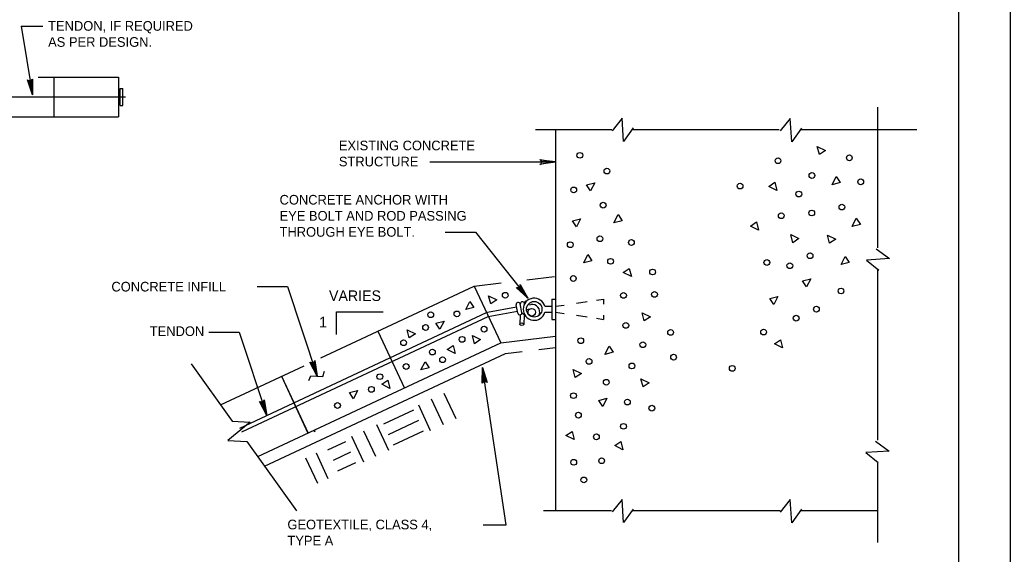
# Model space of a CAD drawing. Extents: x 638850 to 644908, y 297188 to 298900.
# Drawn here: x 640224.3 to 640532.4, y 298330.5 to 298496.6 of the extents above; entities that cross this region are included whole.
import ezdxf

# ---------------------------------------------------------------- set-up
doc = ezdxf.new("R2010")
doc.units = 0
for name, color, linetype in [('1', 7, 'Continuous'), ('3', 7, 'Continuous'), ('PLT-BNDY', 7, 'Continuous')]:
    doc.layers.add(name, color=color, linetype=linetype)

msp = doc.modelspace()

# ---------------------------------------------------------------- linework, layer by layer
at = {"layer": '1'}
for p, q in [((640516.44, 298068.53), (640516.44, 298632.53)), ((640224.78, 298494.68), (640228.26, 298473.3)), ((640255.62, 298470), (640255.62, 298475.29)), ((640256.38, 298470), (640256.38, 298475.29)), ((640077.89, 298472.64), (640257.22, 298472.64)), ((640366.11, 298430.58), (640382.39, 298410.09)), ((640382.12, 298415.82), (640390.71, 298416.87)), ((640307.6, 298413.71), (640316.88, 298385.84)), ((640318.01, 298391.53), (640365.68, 298413.83)), ((640365.68, 298413.83), (640374.04, 298414.84)), ((640365.68, 298413.83), (640373.94, 298396.17)), ((640389.85, 298409.8), (640390.98, 298409.8)), ((640403.75, 298409.46), (640405.9, 298409.78)), ((640369.85, 298405.69), (640378.84, 298407.34)), ((640370.08, 298404.41), (640379.13, 298406.07)), ((640379.25, 298405.39), (640378.77, 298408.04)), ((640380.53, 298405.61), (640380.04, 298408.3)), ((640381.35, 298408.35), (640381.32, 298408.51)), ((640381.98, 298406.59), (640383.52, 298406.87)), ((640382.36, 298407.99), (640383.28, 298408.16)), ((640387.69, 298407.56), (640389.85, 298407.56)), ((640390.98, 298407.56), (640393.69, 298407.96)), ((640397.52, 298408.53), (640400.83, 298409.03)), ((640292.84, 298369.71), (640369.53, 298405.59)), ((640293.39, 298368.53), (640370.08, 298404.41)), ((640322.91, 298398.79), (640322.91, 298405.81)), ((640379.99, 298404.83), (640379.85, 298402)), ((640381.29, 298404.76), (640381.15, 298401.93)), ((640387.69, 298405.72), (640389.85, 298405.72)), ((640389.85, 298403.48), (640390.98, 298403.48)), ((640390.98, 298405.72), (640393.69, 298405.32)), ((640397.52, 298404.75), (640400.83, 298404.25)), ((640403.75, 298403.82), (640405.9, 298403.5)), ((640292.58, 298399.47), (640301.19, 298373.62)), ((640335.71, 298399.81), (640343.97, 298382.15)), ((640373.94, 298396.17), (640390.98, 298398.24)), ((640298.36, 298360.81), (640373.94, 298396.17)), ((640385.84, 298394.15), (640390.98, 298394.77)), ((640300.5, 298357.82), (640375.47, 298392.89)), ((640375.47, 298392.89), (640380.65, 298393.52)), ((640277.67, 298389.7), (640290.43, 298371.88)), ((640286.81, 298376.93), (640312.77, 298389.08)), ((640375.63, 298339.62), (640368.27, 298388.53)), ((640305.74, 298385.79), (640314, 298368.13)), ((640305.79, 298385.81), (640314.06, 298368.15)), ((640352.34, 298378.75), (640356.05, 298370.83)), ((640356.26, 298380.58), (640359.97, 298372.66)), ((640346.8, 298375.3), (640337.45, 298370.92)), ((640348.34, 298376.88), (640352.04, 298368.96)), ((640335.29, 298370.77), (640339, 298362.85)), ((640348.34, 298372.02), (640338.98, 298367.64)), ((640315.87, 298368.58), (640316.33, 298368.79)), ((640315.92, 298368.6), (640316.37, 298368.81)), ((640327.52, 298367.14), (640331.23, 298359.22)), ((640331.25, 298368.88), (640334.95, 298360.96)), ((640349.87, 298368.73), (640340.52, 298364.36)), ((640295, 298365.5), (640310.44, 298343.94)), ((640325.71, 298365.43), (640320.09, 298362.8)), ((640313.25, 298360.46), (640316.95, 298352.54)), ((640316.5, 298361.98), (640320.2, 298354.06)), ((640327.24, 298362.15), (640321.79, 298359.6)), ((640328.78, 298358.87), (640323.22, 298356.27))]:
    msp.add_line(p, q, dxfattribs=at)
for points in [[(640228.09, 298477.95), (640227.79, 298477.72), (640228.26, 298473.3), (640228.09, 298477.95), (640228.26, 298478.21), (640228.26, 298473.3), (640227.33, 298477.64), (640226.98, 298477.75), (640228.26, 298473.3), (640226.72, 298477.96), (640226.98, 298477.75)], [(640415.19, 298463), (640412.18, 298458.77), (640411.72, 298466.01), (640408.62, 298462.1)], [(640467.51, 298462.98), (640464.5, 298458.74), (640464.04, 298465.99), (640460.93, 298462.08)], [(640386.37, 298453.02), (640386.54, 298452.68), (640390.98, 298452.43), (640386.37, 298453.02), (640386.13, 298453.22), (640390.98, 298452.43), (640386.54, 298452.22), (640386.38, 298451.89), (640390.98, 298452.43), (640386.13, 298451.67), (640386.38, 298451.89)], [(640490.7, 298425.39), (640494.93, 298422.38), (640487.69, 298421.92), (640491.6, 298418.81)], [(640379.97, 298414.06), (640379.82, 298413.72), (640382.39, 298410.09), (640379.97, 298414.06), (640379.98, 298414.37), (640382.39, 298410.09), (640379.45, 298413.43), (640379.09, 298413.35), (640382.39, 298410.09), (640378.77, 298413.41), (640379.09, 298413.35)], [(640315.98, 298390.4), (640315.71, 298390.13), (640316.88, 298385.84), (640315.98, 298390.4), (640316.09, 298390.69), (640316.88, 298385.84), (640315.27, 298389.98), (640314.91, 298390.03), (640316.88, 298385.84), (640314.62, 298390.2), (640314.91, 298390.03)], [(640368.38, 298383.88), (640368.69, 298384.1), (640368.27, 298388.53), (640368.38, 298383.88), (640368.22, 298383.62), (640368.27, 298388.53), (640369.15, 298384.18), (640369.5, 298384.06), (640368.27, 298388.53), (640369.75, 298383.85), (640369.5, 298384.06)], [(640314.31, 298384.52), (640314.84, 298385.97), (640318.66, 298385.78), (640319.12, 298387.36)], [(640300.28, 298378.18), (640300.02, 298377.91), (640301.19, 298373.62), (640300.28, 298378.18), (640300.4, 298378.47), (640301.19, 298373.62), (640299.58, 298377.76), (640299.22, 298377.81), (640301.19, 298373.62), (640298.93, 298377.98), (640299.22, 298377.81)], [(640290.43, 298371.88), (640296, 298371.48), (640289.05, 298365.78), (640295, 298365.5)], [(640490.51, 298365.57), (640494.74, 298362.56), (640487.5, 298362.1), (640491.41, 298358.99)], [(640415.19, 298344.51), (640412.18, 298340.28), (640411.72, 298347.52), (640408.62, 298343.61)], [(640467.51, 298344.49), (640464.5, 298340.25), (640464.04, 298347.49), (640460.93, 298343.59)]]:
    msp.add_lwpolyline(points, dxfattribs=at)
for points in [[(640474.97, 298456.02), (640473.08, 298454.75), (640472.44, 298457.28)], [(640457.31, 298444.84), (640459.21, 298446.11), (640459.84, 298443.58)], [(640478.29, 298447.9), (640479.55, 298446), (640477.02, 298445.37)], [(640401.92, 298443.44), (640400.65, 298445.33), (640403.18, 298445.97)], [(640397.54, 298432.23), (640396.28, 298434.12), (640398.81, 298434.76)], [(640410.46, 298436.08), (640411.72, 298434.18), (640409.19, 298433.55)], [(640451.62, 298432.51), (640453.52, 298433.77), (640454.15, 298431.24)], [(640484.56, 298434.92), (640485.83, 298433.03), (640483.3, 298432.39)], [(640466.68, 298428.61), (640464.79, 298427.34), (640464.15, 298429.88)], [(640478.17, 298428.44), (640476.28, 298427.18), (640475.64, 298429.71)], [(640401.02, 298423.63), (640402.29, 298421.73), (640399.76, 298421.1)], [(640481.08, 298423.08), (640482.35, 298421.19), (640479.82, 298420.55)], [(640412.06, 298418.06), (640413.96, 298419.33), (640414.59, 298416.8)], [(640469.11, 298413.59), (640467.85, 298415.49), (640470.38, 298416.12)], [(640372.73, 298409.58), (640370.83, 298408.31), (640370.2, 298410.84)], [(640458.89, 298408.1), (640457.62, 298410), (640460.15, 298410.63)], [(640364.36, 298409.04), (640365.63, 298407.14), (640363.1, 298406.51)], [(640355.04, 298400.45), (640353.78, 298402.34), (640356.31, 298402.97)], [(640420.52, 298404.3), (640418.62, 298403.03), (640417.99, 298405.57)], [(640347.4, 298399.03), (640345.5, 298397.76), (640344.87, 298400.29)], [(640367.69, 298397.19), (640365.79, 298395.92), (640365.16, 298398.45)], [(640459.07, 298395.86), (640460.97, 298397.13), (640461.6, 298394.6)], [(640357.25, 298394.12), (640359.15, 298395.38), (640359.78, 298392.85)], [(640407.66, 298395.15), (640408.92, 298393.25), (640406.39, 298392.62)], [(640350.4, 298390.33), (640351.66, 298388.43), (640349.13, 298387.8)], [(640399.05, 298386.64), (640397.15, 298385.37), (640396.52, 298387.91)], [(640336.95, 298383.3), (640338.85, 298384.57), (640339.48, 298382.04)], [(640420.11, 298383.74), (640418.22, 298382.48), (640417.58, 298385.01)], [(640328.16, 298378.82), (640326.9, 298380.71), (640329.43, 298381.35)], [(640405.72, 298376.42), (640404.46, 298378.31), (640406.99, 298378.95)], [(640394.24, 298367.38), (640396.14, 298368.64), (640396.77, 298366.11)], [(640409.46, 298364.24), (640411.35, 298365.5), (640411.99, 298362.97)]]:
    msp.add_lwpolyline(points, close=True, dxfattribs=at)
for centre, radius in [((640398.55, 298454.5), 0.895), ((640460.21, 298452.81), 0.895), ((640482.4, 298453.71), 0.895), ((640406.98, 298449.59), 0.895), ((640470.75, 298448.22), 0.895), ((640485.93, 298446.27), 0.895), ((640396.65, 298443.74), 0.895), ((640448.4, 298444.95), 0.895), ((640466.69, 298442.47), 0.895), ((640405.82, 298438.99), 0.895), ((640470.7, 298436.57), 0.895), ((640480.08, 298438.41), 0.895), ((640461.21, 298435.72), 0.895), ((640404.82, 298428.55), 0.895), ((640414.62, 298427.39), 0.895), ((640395.6, 298426.71), 0.895), ((640408.14, 298421.54), 0.895), ((640456.73, 298421.17), 0.895), ((640470.17, 298423.28), 0.895), ((640421.21, 298418.22), 0.895), ((640463.9, 298420.17), 0.895), ((640396.54, 298416.21), 0.895), ((640479.81, 298412.31), 0.895), ((640375.36, 298410.99), 0.895), ((640412.14, 298410.94), 0.895), ((640421.79, 298411.26), 0.895), ((640360.34, 298405.19), 0.895), ((640384.37, 298406.64), 2.42), ((640383.62, 298405.7), 1.17), ((640472.17, 298406.67), 0.895), ((640352.17, 298404.93), 0.895), ((640465.85, 298403.87), 0.895), ((640350.59, 298400.97), 0.895), ((640368.77, 298400.45), 0.895), ((640412.88, 298401.61), 0.895), ((640426.8, 298399.44), 0.895), ((640455.73, 298399.55), 0.895), ((640343.73, 298396.23), 0.895), ((640361.92, 298397.28), 0.895), ((640398.86, 298396.86), 0.895), ((640352.69, 298393.33), 0.895), ((640418.15, 298395.59), 0.895), ((640355.86, 298390.95), 0.895), ((640401.45, 298390.43), 0.895), ((640427.74, 298391.74), 0.895), ((640344.53, 298388.84), 0.895), ((640414.78, 298389), 0.895), ((640445.98, 298388.26), 0.895), ((640336.36, 298385.68), 0.895), ((640406.77, 298383.94), 0.895), ((640333.72, 298381.73), 0.895), ((640396.6, 298379.77), 0.895), ((640413.36, 298377.77), 0.895), ((640323.18, 298376.72), 0.895), ((640420.95, 298375.87), 0.895), ((640398.12, 298373.71), 0.895), ((640412.14, 298370.23), 0.895), ((640403.71, 298366.96), 0.895), ((640396.65, 298359.05), 0.895), ((640405.35, 298359.52), 0.895), ((640399.81, 298353.57), 0.895)]:
    msp.add_circle(centre, radius, dxfattribs=at)
for centre, radius, start, end in [((640384.37, 298406.64), 3.44, 15.5072, 344.4928), ((640381.97, 298408.58), 0.651, 82.3401, 186.1378), ((640379.42, 298408.11), 0.651, 17.2813, 186.1378), ((640380.7, 298408.33), 0.651, 17.2813, 186.1378), ((640383.62, 298405.7), 2.48, 340.8483, 97.9455), ((640379.89, 298405.55), 0.651, 194.6568, 3.5133), ((640381.16, 298405.78), 0.651, 194.6568, 276.3379)]:
    msp.add_arc(centre, radius, start, end, dxfattribs=at)
msp.add_ellipse((640380.5, 298401.97), major_axis=(0.648, -0.033), ratio=0.625398, dxfattribs=at)
at = {"layer": '3'}
for p, q in [((640224.78, 298494.68), (640231.54, 298494.67)), ((640230.11, 298478.8), (640255.06, 298478.8)), ((640234.92, 298478.8), (640234.92, 298466.49)), ((640255.06, 298478.8), (640255.06, 298466.49)), ((640255.62, 298475.29), (640256.38, 298475.29)), ((640255.62, 298470), (640256.38, 298470)), ((640491.16, 298469.44), (640491.16, 298425.72)), ((640079.26, 298466.49), (640255.06, 298466.49)), ((640384.73, 298462.54), (640408.47, 298462.54)), ((640390.98, 298462.54), (640390.98, 298344.05)), ((640414.89, 298462.54), (640460.59, 298462.54)), ((640467.39, 298462.54), (640503.42, 298462.54)), ((640351.89, 298452.48), (640390.98, 298452.43)), ((640356.64, 298430.6), (640366.11, 298430.58)), ((640491.16, 298419.21), (640491.16, 298365.9)), ((640298.14, 298413.72), (640307.6, 298413.71)), ((640389.85, 298409.8), (640389.85, 298403.48)), ((640405.9, 298409.78), (640405.9, 298408.25)), ((640322.91, 298405.81), (640337.41, 298405.79)), ((640405.9, 298404.82), (640405.9, 298403.5)), ((640283.11, 298399.48), (640292.58, 298399.47)), ((640491.16, 298358.81), (640491.16, 298334.08)), ((640387.24, 298344.05), (640408.46, 298344.05)), ((640414.89, 298344.05), (640460.59, 298344.05)), ((640415.18, 298344.05), (640460.9, 298344.05)), ((640467.35, 298344.05), (640491.16, 298344.05)), ((640368.49, 298339.63), (640375.63, 298339.62))]:
    msp.add_line(p, q, dxfattribs=at)
at = {"layer": 'PLT-BNDY'}
msp.add_lwpolyline([(639691.44, 298647.53), (640532.44, 298647.53), (640532.44, 298053.53), (639691.44, 298053.53)], close=True, dxfattribs=at)

# ---------------------------------------------------------------- texts
at = {"layer": '1'}
for s, height, p in [('TENDON, IF REQUIRED', 3, (640233.16, 298493.24)), ('AS PER DESIGN.', 3, (640233.16, 298488.24)), ('EXISTING CONCRETE', 3, (640323.6, 298456.06)), ('STRUCTURE', 3, (640323.6, 298451.06)), ('CONCRETE ANCHOR WITH', 3, (640305.16, 298439.19)), ('EYE BOLT AND ROD PASSING', 3, (640305.16, 298434.19)), ('THROUGH EYE BOLT.', 3, (640305.16, 298429.19)), ('CONCRETE INFILL', 3, (640252.85, 298412.16)), ('VARIES', 3.3, (640320.53, 298409.2)), ('1', 3.3, (640317.44, 298401)), ('TENDON', 3, (640264.79, 298398.32)), ('GEOTEXTILE, CLASS 4,', 3, (640307.6, 298338.2)), ('TYPE A', 3, (640307.6, 298333.2))]:
    msp.add_text(s, height=height, dxfattribs=at).set_placement(p)

doc.saveas('drawing.dxf')
